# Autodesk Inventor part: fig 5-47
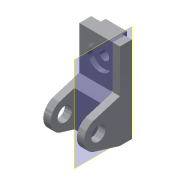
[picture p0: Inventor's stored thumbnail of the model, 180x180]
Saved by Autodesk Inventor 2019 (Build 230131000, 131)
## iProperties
Shininess: 65.0
Angle Display Precision: 2
Document Length Units: 11269
Document Angle Units: 11279
Document Time Units: 11290
Document Mass Units: 11283
Document Length Units Precision: 3
Document Angle Units Precision: 2
Created: 2001-11
Part Number: fig 5-47
Document SubType Name: Modeling
Designer: Renu Muthoo
Density: 1 g/cm^3
Material: Generic
Appearance: Aluminum - Flat
Density: 0.0
Volumn: 0.0
Area: 0.0
PropertySet Name: Model Information
Control State: 0
Master: False
Checked Out: False
Author: Renu Muthoo
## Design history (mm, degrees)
node "Sketch1"
sketch "Sketch2"
  geometry: L1 (33.257, 104.664)-(33.257, -75.336); L2 (33.257, -75.336)-(8.257, -75.336); L3 (8.257, -75.336)-(-45.451, -59.045); L4 (-45.451, -1.628)-(8.257, 14.664); L5 (8.257, 14.664)-(8.257, 104.664); L6 (8.257, 104.664)-(33.257, 104.664); C1 r 15 at (-36.743, -30.336); A1 r 30 centre (-36.743, -30.336) between (-45.451, -1.628) and (-45.451, -59.045)
  constraints: 12 end point, 2 centre point, 2 equal length, 2 parallel, 2 point on circle, 2 tangent, 1 coincident, 1 perpendicular, 1 vertical
  dimensions: "d0" = 180 distance of L1.start L1.end; "d1" = 30 radius of A1; "d2" = 25 distance of L5.end L1.start; "d3" = 45 distance from line of L2 A1.centre; "d4" = 70 distance from line of L1 A1.centre; "d5" = 30 diameter of C1
extrude "Extrusion1" new body sketch "Sketch2" distance "d6" = 85; taper "d7" = 0 deg
workplane "Work Plane1"
sketch "Sketch3"
  geometry: L1 (15, 62.364)-(70, 62.364); L2 (70, 62.364)-(70, -52.386); L3 (70, -52.386)-(15, -52.386); L4 (15, -52.386)-(15, 62.364); L5 (0, -45)-(0, -28.708) reference
  constraints: 8 end point, 2 parallel, 1 horizontal, 1 perpendicular
  dimensions: "d8" = 55 distance of L1.start L1.end; "d9" = 15 distance between parallel lines of L5 L4
extrude "Extrusion2" cut sketch "Sketch3" distance "d10" = 50; taper "d11" = 0 deg
sketch "Sketch4"
  geometry: L1 (0, 25)-(85, 25) reference; L2 (0, 0)-(0, 25) reference; L3 (20, 25)-(65, 25); L4 (65, 25)-(65, 35); L5 (65, 35)-(20, 35); L6 (20, 35)-(20, 25)
  constraints: 8 end point, 2 parallel, 1 horizontal, 1 perpendicular, 1 point on line
  dimensions: "d12" = 45 distance of L4.end L5.end; "d13" = 10 distance of L3.end L4.end; "d14" = 20 distance between parallel lines of L2 L6
extrude "Extrusion3" join sketch "Sketch4" stored distance "d15" = 50; taper "d16" = 0 deg
sketch "Sketch5"
  geometry: L1 (85, 0)-(85, 90) reference; L2 (0, 90)-(85, 90) reference; 1 further point
  dimensions: "d17" = 42 distance from line of L2 point (42.5, 48); "d18" = 42.5 distance from line of L1 point (42.5, 48)
hole "Hole1" sketch "Sketch5" at (42.5, 48) diameter "d19" = 20; stored, may be unused: countersink angle "d23" = 82 deg, drill point angle "d25" = 118 deg; dims "d20" = 6, "d21" = 50, "d22" = 10, "d24" = 8
workplane "Work Plane7"
workpoint "Work Point7"
workpoint "Work Point8"
body "Solid1"
other parameters: "d29" = 0
